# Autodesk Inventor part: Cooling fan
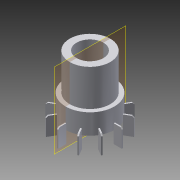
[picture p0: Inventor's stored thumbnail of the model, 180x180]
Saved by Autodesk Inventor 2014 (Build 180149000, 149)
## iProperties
Created: 2008-06
Part Number: Cooling fan
Document SubType Name: Modeling
Designer: tangg
Density: 1.4 g/cm^3
Mass: 5.22571 g
Surface Area: 24.131 cm^2
Volume: 5.22571 cm^3
Stock Number: Cooling fan
Material: PVC-U
Appearance: Snow
Author: tangg
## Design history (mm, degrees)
sketch "Sketch1"
  geometry: L1 (0, 0)-(7.938, 0); L2 (7.938, 0)-(7.938, -14.287); L3 (7.938, -14.287)-(0, -14.287); L4 (0, -14.287)-(0, 0); L5 (0, -14.287)-(9.525, -14.287); L6 (9.525, -14.287)-(9.525, -22.225); L7 (9.525, -22.225)-(0, -22.225); L8 (0, -22.225)-(0, -14.287)
  constraints: 16 end point
revolve "Revolution1" sketch "Sketch1" stored, may be unused: angle "d0" = 90 deg
sketch "Sketch2"
  geometry: L1 (-14.287, 7.938)-(-14.287, -7.938) reference; L2 (0, 7.938)-(0, -7.938) reference; L3 (-14.287, -9.525)-(-22.225, -9.525) reference; L4 (-19.831, -9.525)-(-26.889, -9.525); L5 (-26.889, -9.525)-(-26.889, -12.7); L6 (-26.889, -12.7)-(-20.466, -12.7); L7 (-19.831, -12.065)-(-19.831, -9.525); L8 (-20.466, -12.7)-(-19.831, -12.065); 2 further points
  constraints: 10 end point, 3 point on line
  dimensions: "d1" = 0.635 distance of L6.end point (-19.831, -12.7); "d2" = 0.635 distance of L7.start point (-19.831, -12.7) (= d1)
extrude "Extrusion1" join sketch "Sketch2" stored distance "d3" = 0.508; taper "d4" = 0 deg
pattern_circular "Circular Pattern1" dims angle "d6" = 360 deg
sketch "Sketch3"
  geometry: C1 r 5.25 at (0, 0); 1 further point
  constraints: 1 centre point, 1 coincident
  dimensions: "d10" = 10.5 diameter of C1
extrude "Extrusion2" cut sketch "Sketch3" stored distance "d8" = 10; taper "d9" = 0 deg
body "Solid1"
node "Projected Loop1"
